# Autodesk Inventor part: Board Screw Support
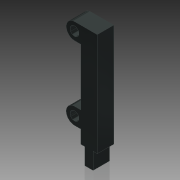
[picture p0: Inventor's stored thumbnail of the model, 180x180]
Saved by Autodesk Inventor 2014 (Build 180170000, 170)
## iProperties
Created: 2015-07
Part Number: Board Screw Support
Material: Generic
Document SubType Name: Modeling
Designer: Brad Factor
Density: 1 g/cm^3
Appearance: Gunmetal - Polished
Author: Brad Factor
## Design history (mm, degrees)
sketch "Sketch1"
  geometry: L1 (8.731, 39.599)-(2.381, 39.599); L2 (2.381, 39.599)-(2.381, 38.524); L3 (2.381, 0)-(3.969, 0); L4 (8.731, 0)-(8.731, 39.599); L5 (0, 5.055)-(2.381, 5.055); L6 (0, 11.405)-(2.381, 11.405); L7 (0, 39.599)-(2.381, 39.599); L8 (0, 33.249)-(2.381, 33.249); L9 (2.381, 11.405)-(2.381, 5.055); L10 (2.381, 5.055)-(2.381, 0); L11 (2.381, 38.524)-(2.381, 34.324); L12 (2.381, 33.249)-(2.381, 11.405); L13 (2.381, 34.324)-(2.381, 33.249); L14 (7.144, 0)-(7.144, -6.35); L15 (7.144, -6.35)-(3.969, -6.35); L16 (3.969, -6.35)-(3.969, 0); L17 (7.144, 0)-(8.731, 0); L18 (3.969, 0)-(7.144, 0); L19 (3.175, 39.599)-(3.175, 38.767); L20 (3.175, 38.767)-(3.175, 0); A1 r 3.175 centre (0, 36.424) between (0, 39.599) and (0, 33.249); A2 r 3.175 centre (0, 8.23) between (0, 11.405) and (0, 5.055); A3 r 3.175 centre (0, 36.424) between (2.381, 38.524) and (0, 39.599); A4 r 3.175 centre (0, 36.424) between (2.381, 34.324) and (2.381, 38.524); A5 r 3.175 centre (0, 36.424) between (0, 33.249) and (2.381, 34.324); A6 r 3.175 centre (0, 8.23) between (2.381, 10.33) and (0, 11.405); A7 r 3.175 centre (0, 8.23) between (2.381, 6.13) and (2.381, 10.33); A8 r 3.175 centre (0, 8.23) between (0, 5.055) and (2.381, 6.13); 3 further points
  constraints: 40 end point, 18 point on circle, 13 tangent, 10 parallel, 9 point on line, 8 centre point, 7 perpendicular, 6 horizontal, 3 vertical alignment, 1 equal radius, 1 horizontal alignment, 1 midpoint, 1 vertical
  dimensions: "d0" = 6.35 diameter of A1; "d1" = 28.194 distance of A2.centre A1.centre; "d2" = 8.2296 distance of point (0, 0) A2.centre; "d3" = 6.35 distance of L3.start L4.start; "d5" = 3.175 distance of L14.end L15.end; "d6" = 6.35 distance of L14.start L14.end; "d7" = 1.5875 distance between parallel lines of L10 L16; "d10" = 0.79375 distance between parallel lines of L20 L12
extrude "Base" new body sketch "Sketch1" distance "d8" = 6.35; taper "d9" = 0 deg
sketch "Sketch2"
  geometry: A1 r 3.175 centre (0, 36.424) between (0, 39.599) and (0, 33.249) reference; A2 r 3.175 centre (0, 8.23) between (0, 11.405) and (0, 5.055) reference; 3 further points
  constraints: 2 coincident
hole "#4 Clearance Holes" sketch "Sketch2" at (0, 36.424), (0, 8.23) diameter "d11" = 3.4544; stored, may be unused: countersink angle "d15" = 82 deg, drill point angle "d17" = 118 deg; dims "d12" = 19.05, "d13" = 5.5626, "d14" = 2.8448, "d16" = 25.4
body "Solid1"
